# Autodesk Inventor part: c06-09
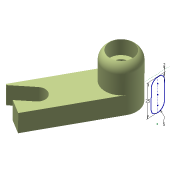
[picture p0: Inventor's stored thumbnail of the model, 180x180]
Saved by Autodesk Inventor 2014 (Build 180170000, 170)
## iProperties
Created: 2013-03
Part Number: c06-09
Material: Aluminum 6061
Document SubType Name: Modeling
Designer: Thom Tremblay
Density: 2.71 g/cm^3
Appearance: Zinc Chromate 2
Author: Thom Tremblay
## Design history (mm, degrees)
sketch "Sketch1"
  geometry: L1 (0, -12.5)-(60, -12.5); L2 (60, -12.5)-(60, 12.5); L3 (60, 12.5)-(0, 12.5); L4 (0, 12.5)-(0, -12.5); 2 further points
  constraints: 8 end point, 2 parallel, 1 coincident, 1 horizontal, 1 midpoint, 1 perpendicular
  dimensions: "d1" = 25 distance of L2.end L1.end; "d2" = 60 distance of L2.end L3.end
extrude "Base" new body sketch "Sketch1" distance "d3" = 14; taper "d4" = 0 deg
sketch "Sketch2"
  geometry: C1 r 12.5 at (0, 0); 1 further point
  constraints: 1 centre point, 1 coincident
extrude "Boss" join sketch "Sketch2" distance "d5" = 35; taper "d6" = 0 deg
sketch "Sketch3"
  geometry: L1 (-60, 12.5)-(-60, -12.5) reference; L2 (-60, -6)-(-60, 6); L3 (-43.948, 5.638)-(-60, 11.481); L4 (-48.052, -5.638)-(-60, -1.289); L5 (-60, 11.481)-(-60, -1.289); A1 r 6 centre (-46, 0) between (-43.948, 5.638) and (-48.052, -5.638); 2 further points
  constraints: 8 end point, 3 midpoint, 2 point on circle, 2 point on line, 2 tangent, 1 centre point, 1 collinear, 1 horizontal alignment, 1 parallel
  dimensions: "d8" = 12 diameter of A1; "d20" = 20 dimension on A1 L1; "d27" = 70 deg angle of L1 L3
extrude "Slot" cut sketch "Sketch3" stored distance "d9" = 24; taper "d10" = 0 deg
hole "Hole1" diameter "d13" = 11; stored, may be unused: countersink angle "d17" = 90 deg, drill point angle "d19" = 118 deg; dims "d11" = 10, "d12" = 10, "d14" = 6, "d15" = 18, "d16" = 11, "d18" = 8
fillet "Fillet1" dims "d26" = 8
node "Midplane between faces"
node "Normal to Edge at Point"
node "Offset Plane"
  node "Tangent Plane"
sketch "Sketch4"
  geometry: L1 (0, 0)-(-60, 0) reference; L2 (-14, 0)-(-18.341, 24.62)
  constraints: 2 end point, 1 point on line
  dimensions: "d21" = 25 distance of L2.start L2.end; "d22" = 80 deg angle of L1 L2; "d23" = 14 distance of L1.start L2.start
node "Plane at Angle on Sketch"
sketch "Sketch5"
  geometry: L1 (0, 0)-(-19.151, 16.07); L2 (0, 0)-(25, 0); C1 r 9 at (0, 0) reference; C2 r 5.5 at (0, 0) reference
  constraints: 4 end point, 1 equal length, 1 horizontal
  dimensions: "d24" = 25 distance of L1.start L1.end; "d25" = 140 deg angle of L2 L1
node "Plane using Sketch as Axis"
sketch "Sketch6"
  geometry: L1 (33, 0)-(8, 0); L2 (28, -5)-(13, -5); L3 (13, 5)-(28, 5); L4 (35, 9)-(35, -9) reference; A1 r 5 centre (28, 0) between (28, -5) and (28, 5); A2 r 5 centre (13, 0) between (13, 5) and (13, -5); 2 further points
  constraints: 8 end point, 6 point on circle, 4 tangent, 3 point on line, 2 centre point, 1 horizontal, 1 midpoint, 1 parallel
  dimensions: "d33" = 2 distance from line of L1.start L4; "d34" = 25 distance of L1.start L1.end; "d35" = 5 radius of A2
sketch "Sketch7"
  geometry: L1 (-18.138, 14)-(-6.5, 14) reference; L2 (-16.5, 14)-(-16.5, 21); L3 (-8.5, 21)-(-8.5, 14); A1 r 4 centre (-12.5, 21) between (-8.5, 21) and (-16.5, 21); 2 further points
  constraints: 4 end point, 2 perpendicular, 2 point on circle, 2 point on line, 2 tangent, 1 centre point, 1 vertical alignment
  dimensions: "d31" = 7 distance of L3.start L3.end; "d32" = 4 radius of A1
sketch "Sketch8"
  geometry: L1 (0, 9)-(0, -9) reference; C1 r 3.5 at (0, 0); 1 further point
  constraints: 1 centre point, 1 midpoint
  dimensions: "d36" = 7 diameter of C1
body "Solid1"
workaxis "Work Axis1"
node "Plane at Angle"
other parameters: "d28" = 30 deg, "d29" = 15, "d30" = 90 deg
